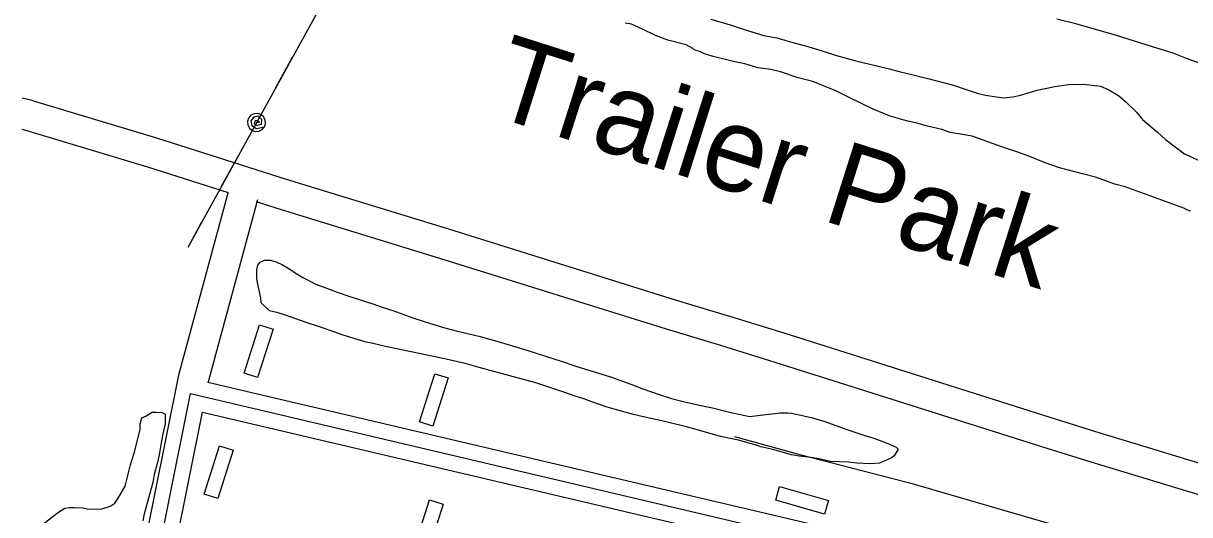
# Model space of a CAD drawing. Extents: x 3297735 to 3335592, y 670436 to 695807.
# Drawn here: x 3304997 to 3306147, y 678908 to 679392 of the extents above; entities that cross this region are included whole.
import ezdxf

# ---------------------------------------------------------------- set-up
doc = ezdxf.new("R2010")
doc.units = 0
for name, color, linetype in [('V-BLDG-IDEN', 7, 'Continuous'), ('V-BLDG-OTLN', 7, 'Continuous'), ('V-ROAD-CNTR', 7, 'Continuous'), ('V-SITE-VEGE', 7, 'Continuous'), ('V-TOPO-SHOR', 7, 'Continuous'), ('V-UTIL-LINE', 7, 'Continuous')]:
    doc.layers.add(name, color=color, linetype=linetype)

msp = doc.modelspace()

# ---------------------------------------------------------------- linework, layer by layer
at = {"layer": 'V-BLDG-OTLN'}
for points in [[(3305214.3, 679047.3), (3305229.4, 679095), (3305242.8, 679090.7), (3305227.6, 679043.1)], [(3305387, 678999.1), (3305402.2, 679046.7), (3305415.5, 679042.5), (3305400.3, 678994.8)], [(3305174.9, 678927.9), (3305190.1, 678975.6), (3305203.4, 678971.3), (3305188.2, 678923.7)], [(3305742.2, 678935.3), (3305790.3, 678921.6), (3305786.5, 678908.1), (3305738.4, 678921.9)], [(3305381.9, 678874.6), (3305397.1, 678922.2), (3305410.4, 678918), (3305395.3, 678870.4)]]:
    msp.add_lwpolyline(points, close=True, dxfattribs=at)
at = {"layer": 'V-ROAD-CNTR'}
for p, q in [((3305198.3, 679224.8), (3305149.7, 679045.4)), ((3305227.6, 679218.2), (3305178.6, 679037.5))]:
    msp.add_line(p, q, dxfattribs=at)
for points in [[(3306188.1, 678948.9), (3306144.7, 678961.8), (3306101.5, 678974.9), (3306058.3, 678988.1), (3306015.1, 679001.6), (3305746.7, 679086.6), (3305693.1, 679103.2), (3305639.6, 679119.4), (3305416.2, 679189.2), (3305255.9, 679238.4), (3305128.2, 679279.1), (3305008, 679315.3), (3305004.2, 679316.5), (3304999.8, 679317.7), (3304995.3, 679318.7)], [(3305198.9, 679225.1), (3305119.3, 679250.4), (3304998.9, 679286.7), (3304995.5, 679287.8)], [(3306179.6, 678920.1), (3306136.1, 678933.1), (3306092.7, 678946.2), (3306049.4, 678959.5), (3306006.1, 678973), (3305737.7, 679057.9), (3305684.3, 679074.5), (3305630.7, 679090.7), (3305407.3, 679160.5), (3305246.9, 679209.8), (3305226.6, 679216.3)], [(3305072.5, 678656.5), (3305077.4, 678683.9), (3305149.8, 679045.2)], [(3305178.5, 679038.5), (3305935.2, 678860.3), (3306571.7, 678708.8), (3306918.9, 678631.8)], [(3305008.4, 678172.2), (3305075.4, 678586.7), (3305092.1, 678681.1), (3305161.5, 679027.1), (3305931.8, 678845.7), (3306568.3, 678694.1), (3307255.3, 678541.8)], [(3305101.9, 678650), (3305106.9, 678678.3), (3305173.1, 679008.9), (3305928.3, 678831.1), (3306565, 678679.5), (3307252, 678527.2)]]:
    msp.add_lwpolyline(points, dxfattribs=at)
at = {"layer": 'V-SITE-VEGE'}
for points in [[(3306147.2, 679207.1), (3306143.8, 679208.5), (3306140.8, 679210), (3306083, 679231), (3306072.7, 679233.8), (3306053.6, 679240.5), (3306040.8, 679243.8), (3306018.3, 679250), (3306004.1, 679254.8), (3305987.9, 679261.5), (3305977.1, 679265.3), (3305960.4, 679271), (3305932, 679281.1), (3305924.6, 679282.5), (3305910.4, 679284.8), (3305902.1, 679287.6), (3305887.9, 679290.9), (3305877.6, 679293.8), (3305867.3, 679296.2), (3305851.1, 679300.9), (3305834.5, 679307.6), (3305810.9, 679319.1), (3305797.6, 679325.9), (3305775.1, 679335), (3305760.4, 679338.8), (3305743.2, 679344.5), (3305733.4, 679346.9), (3305720.7, 679348.7), (3305708, 679352.5), (3305698.2, 679354.4), (3305676.6, 679359.6), (3305668.3, 679362.4), (3305664.3, 679364.4), (3305658, 679366.3), (3305656.5, 679367.7), (3305650.1, 679371.1), (3305632, 679375.8), (3305619.7, 679380.6), (3305606.5, 679386.9), (3305601.1, 679389.3), (3305596.2, 679391.7), (3305589.8, 679392.6)], [(3305674.3, 679396.7), (3305693.5, 679391), (3305706.2, 679386.7), (3305726.8, 679380.5), (3305739.5, 679378.2), (3305755.2, 679373.4), (3305767.9, 679370.1), (3305785.1, 679364.9), (3305798.3, 679360.6), (3305817.4, 679355.4), (3305829.7, 679352.6), (3305848.8, 679347.8), (3305861.5, 679344.5), (3305873.8, 679341.7), (3305888.5, 679337.9), (3305913.5, 679331.3), (3305924.3, 679327.9), (3305937, 679323.6), (3305945.3, 679321.7), (3305956.1, 679319.9), (3305962.5, 679319), (3305972.2, 679320), (3305979.6, 679321.5), (3305996.1, 679326.6), (3306013.7, 679330.1), (3306026.9, 679332.2), (3306042, 679332.3), (3306058.7, 679330.5), (3306066, 679327.2), (3306076.4, 679321.4)], [(3306158.2, 679352.4), (3306143.5, 679357.6), (3306130.3, 679362.9), (3306109.7, 679369.1), (3306074.4, 679380.5), (3306034.2, 679391.9), (3306015.6, 679396.6)], [(3306076.4, 679321.4), (3306083.7, 679315.1), (3306094.1, 679304.9), (3306100, 679297.6)], [(3306100, 679297.6), (3306114.8, 679285), (3306122.7, 679277.8), (3306133.5, 679269.5), (3306141.4, 679263.7), (3306166.9, 679251.7)], [(3305734.1, 679007), (3305737.9, 679007.3), (3305742.3, 679008.1), (3305750.3, 679008.1), (3305753.9, 679007.8), (3305766.2, 679005.3), (3305774.7, 679003.1), (3305786.8, 678999.7), (3305807.4, 678992), (3305815.4, 678989.2), (3305827.2, 678985.3), (3305835.1, 678983.1), (3305845.6, 678979), (3305851.3, 678977), (3305857.1, 678974.3), (3305859, 678972.3), (3305855.1, 678965.8), (3305852.4, 678963.6), (3305840.8, 678958.4), (3305831.8, 678957.9), (3305818.3, 678958.4), (3305810.1, 678959.3), (3305792.5, 678960.2), (3305780.9, 678962.7), (3305773.3, 678964.1), (3305761.4, 678965.2), (3305754, 678966.6), (3305735.6, 678971.9), (3305723.8, 678974.6), (3305720, 678976), (3305703, 678980.7), (3305698.3, 678981.8), (3305684, 678984.9), (3305660.1, 678991.6), (3305650.5, 678994.3), (3305635.7, 678998), (3305626.1, 679000.2), (3305609.3, 679003.8), (3305598.1, 679006.6), (3305581.3, 679011), (3305571.1, 679014.1), (3305557.1, 679018.8), (3305549.2, 679021.8), (3305539.8, 679024.9), (3305530.5, 679028.2), (3305513.8, 679033.7), (3305501.7, 679037.6), (3305480, 679043.7), (3305445.9, 679052.9), (3305432.2, 679056.8), (3305413.5, 679061.2), (3305378.9, 679068.4), (3305354.8, 679073.2), (3305339.9, 679076.8), (3305334.7, 679077.9), (3305311.9, 679084.6), (3305298.2, 679089.8), (3305288.6, 679092.9), (3305275.4, 679097.3), (3305255.1, 679104.5), (3305247.7, 679106.7), (3305239.2, 679108.9), (3305231.2, 679116.7), (3305230.7, 679121.3), (3305229.9, 679126), (3305227.7, 679135.1), (3305226.9, 679140.8), (3305226.9, 679149.9), (3305227.8, 679153.8), (3305230, 679156.8), (3305231.9, 679157.9), (3305234.4, 679158.7), (3305239.9, 679158.7), (3305245.9, 679157), (3305252.2, 679154), (3305257.7, 679150.9), (3305266.2, 679145.4), (3305272, 679141.8), (3305285.1, 679135.2), (3305299.1, 679129.7), (3305306, 679127.2), (3305318.6, 679123), (3305341.1, 679115.8), (3305351.3, 679112.2), (3305362, 679108.6), (3305379.6, 679102.2), (3305391.9, 679098.1), (3305410.9, 679092.3), (3305424.6, 679088.7), (3305445.5, 679083.7), (3305458.7, 679080), (3305479, 679074.2), (3305493, 679069.8), (3305527.9, 679058.7), (3305541.3, 679054), (3305576.4, 679043.2), (3305595.4, 679036.5), (3305607.5, 679031.8), (3305624.5, 679026), (3305635.7, 679022.4), (3305647, 679019.4)], [(3305647, 679019.4), (3305664.6, 679015.2), (3305676.1, 679013), (3305694, 679008.5), (3305703.8, 679006.6), (3305712.6, 679004.6), (3305734.1, 679007)], [(3305111.6, 678992.1), (3305111.6, 678997.4), (3305113.5, 679003.3), (3305117.9, 679005.3), (3305123.2, 679008.8), (3305127.1, 679008.8), (3305133, 679008.4), (3305136.4, 679006.9), (3305136.5, 678997.2), (3305133.7, 678985.9), (3305132.3, 678978.6), (3305130.4, 678966.8), (3305129, 678959), (3305125.7, 678947.2), (3305124.3, 678939.4), (3305121, 678927.6), (3305119.1, 678920.3), (3305115.7, 678908.5), (3305114.3, 678901.6)], [(3304994.3, 678876.2), (3305002.5, 678886), (3305009.3, 678892.5), (3305015.6, 678897.9), (3305024.3, 678904.8), (3305030.2, 678909.3), (3305037.5, 678914.2), (3305041.9, 678914.7), (3305046.7, 678914.8), (3305055.1, 678914.3), (3305059.5, 678913.4), (3305069.3, 678913), (3305074.1, 678913.5), (3305080.5, 678915.5), (3305082.9, 678916.5), (3305086.8, 678919), (3305090.2, 678923.9), (3305096.9, 678935.7), (3305102.1, 678956.8), (3305106.4, 678970.5), (3305111.6, 678992.1)]]:
    msp.add_lwpolyline(points, dxfattribs=at)
at = {"layer": 'V-TOPO-SHOR'}
msp.add_lwpolyline([(3306884.8, 678658.5), (3306760.7, 678693.6), (3306637.8, 678728), (3306491.1, 678764.9), (3306382.7, 678794), (3306265.6, 678827.7), (3306145.4, 678857.8), (3306016.6, 678896.4), (3305874.2, 678937.7), (3305763.4, 678966.3), (3305697.9, 678984.4)], dxfattribs=at)
at = {"layer": 'V-UTIL-LINE'}
for points in [[(3307600.6, 683492.8), (3306458.1, 681495.3), (3305771.9, 680286.2), (3305158.6, 679171.3)], [(3305261.7, 679358.6), (3305245.3, 679328.8)], [(3305226.5, 679294.7), (3305229.3, 679295), (3305227.8, 679296.7), (3305225.1, 679296.4), (3305224, 679293.7), (3305226.9, 679291.9), (3305231.4, 679293.1), (3305231.7, 679297.4), (3305228.2, 679300.8), (3305223.8, 679299.7), (3305220.8, 679296.3), (3305221.7, 679291.6), (3305226.4, 679288.7), (3305234.4, 679290.3), (3305235.4, 679293.7), (3305235.1, 679297.2), (3305233.5, 679300.3), (3305230.8, 679302.6), (3305227.5, 679303.6), (3305224, 679303.3), (3305220.9, 679301.7), (3305218.6, 679299), (3305217.5, 679295.7), (3305217.8, 679292.2), (3305219.5, 679289.1), (3305222.1, 679286.8), (3305225.5, 679285.7), (3305229, 679286), (3305232.1, 679287.7), (3305234.4, 679290.3)], [(3305207.7, 679260.5), (3305191.3, 679230.7)], [(3305172, 679195.7), (3305158.6, 679171.3)]]:
    msp.add_lwpolyline(points, dxfattribs=at)

# ---------------------------------------------------------------- texts
at = {"layer": 'V-BLDG-IDEN'}
msp.add_text('Trailer Park', height=83, rotation=342.3961, dxfattribs=at).set_placement((3305453.1, 679303.1))

doc.saveas('drawing.dxf')
